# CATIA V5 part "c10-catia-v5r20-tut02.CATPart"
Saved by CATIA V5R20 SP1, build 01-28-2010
Part number: tut2
Bounding box of the stored display mesh (mm): x -104.999 to 104.999, y -155 to 550, z -22.499 to 22.486
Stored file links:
  D:\v5_r20\psrt_files_downloaded\c10\c10-catia-v5r20-tut02.CATPart
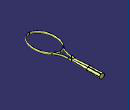
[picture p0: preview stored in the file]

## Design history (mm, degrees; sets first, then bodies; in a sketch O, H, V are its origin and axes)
Body1 (main body)
  Sketch1 on xy-plane, origin (0, 0, 0), H (1, 0, 0), V (0, 1, 0)
    ellipse A1 centre (0, 0) semi-axes 150, 100 rotation 90
    point P1 (100, 0)
    "Radius" A1 = 150
    "Radius" A1 = 100
    coincidence: P1 H, A1 P1
    vertical: A1 V
  Sketch2 on zx-plane, origin (0, 0, 0), H (-1, 0, 0), V (0, 0, 1)
    point P1 (100, 0)
    ellipse A1 centre (100, 0) semi-axes 10, 5 rotation 90
    point P2 (105, 0)
    reference projected line E1 (-100, 0) -> (100, 0) from Sketch1.A1
    "Radius" A1 = 10
    "Radius" A1 = 5
    distance V P1 = 100
    coincidence: P2 H, A1 P2, P1 E1
    vertical: A1 V
  Sweep1: type Unspec, Profile Sketch2, Guide Sketch1
  Sketch3 on xy-plane, origin (0, 0, 0), H (1, 0, 0), V (0, 1, 0)
    line L1 (15, 275) -> (15, 245)
    point P1 (15, 275)
    arc A1 centre (215, 245) radius 200 from (15, 245) to (55, 125) ccw
    point P4 (55, 125)
    radius A1 = 200
    distance L1 V = 15
    distance H P1 = 275
    distance H P4 = 125
    distance P4 V = 55
    vertical: L1 V
    tangency: A1 L1
  Plane1: type Normal, Curve Sketch3, RefPoint Sketch3.P1
  Sketch4 on Plane1, origin (0, 275, 0), H (1, 0, 0), V (0, 0, 1)
    point P1 (15, 0)
    ellipse A1 centre (15, 0) semi-axes 8.75, 4.5 rotation 90
    reference projected point E1 (15, 0) from Sketch3.P1
    "Radius" A1 = 8.75
    "Radius" A1 = 4.5
    vertical: A1 V
    coincidence: P1 E1
  Sweep2: type Unspec, Profile Sketch4, Guide Sketch3
  Symmetry1: ToTransfor Sweep2, Reference yz-plane
  Sketch5 on Plane1, origin (0, 275, 0), H (1, 0, 0), V (0, 0, 1)
    projected curve E1 from Sketch4.A1
    projected curve E2 from Sketch4.A1
    projected curve E3 from edge of Symmetry1
    projected curve E4 from edge of Symmetry1
    line L1 (11.75, 6.052) -> (-11.75, 6.052)
    point P1 (11.75, 6.052)
    point P2 (-11.75, 6.052)
    point P3 (-11.75, -6.052)
    point P4 (11.75, -6.052)
    line L2 (11.75, -6.052) -> (-11.75, -6.052)
    point P5 (-11.75, -6.052)
    length L1 = 23.5
    horizontal: L1 H
    coincidence: P1 E1, P2 E3, L2 P5
    symmetry: P2 P3 H, P1 P4 H, L1 L2 H
  Plane2: type Offset, RefPlane zx-plane, Offset 425
  Sketch6 on Plane2, origin (0, 425, 0), H (-1, 0, 0), V (0, 0, 1)
    ellipse A1 centre (0, 0) semi-axes 22.5, 20 rotation 0
    point P1 (22.5, 0)
    point P2 (0, 20)
    point P3 (-11.75, 17.0562)
    point P4 (11.75, 17.0562)
    point P5 (11.75, -17.0562)
    point P6 (-11.75, -17.0562)
    "Radius" A1 = 22.5
    "Radius" A1 = 20
    distance V P3 = 11.75
    distance P3 P4 = 23.5
    distance P6 P5 H = 23.5
    distance P6 V = 11.75
    coincidence: P1 H, P2 V, A1 P1, A1 P2, P3 A1, P4 A1, P6 A1, A1 P5
    horizontal: A1 H
  Loft1: Sections (Sketch5; Sketch6.A1), SectionCouplingPoints ({coupling CouplingPoints (vertex [element of Sketch5 | element of Sketch5]; Sketch6.P4)}; {coupling CouplingPoints (vertex [element of Sketch5 | element of Sketch5]; Sketch6.P5)}; {coupling CouplingPoints (vertex [element of Sketch5 | element of Sketch5]; Sketch6.P6)}; {coupling CouplingPoints (vertex [element of Sketch5 | element of Sketch5]; Sketch6.P3)})
  Plane3: type Offset, RefPlane zx-plane, Offset 550
  Sketch7 on Plane3, origin (0, 550, 0), H (-1, 0, 0), V (0, 0, 1)
    circle A1 centre (0, 0) radius 22.5
    radius A1 = 22.5
  Blend1: StartLimit {blendlimit Curve edge of Loft1, Point {extremum Reference edge of Loft1, Direction (1, 2, 3)}}, EndLimit {blendlimit Curve Sketch7, Point {extremum Reference Sketch7, Direction (1, 2, 3)}}
  Fill1: Boundary edge of Blend1
  Fill2: Boundary Sketch5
